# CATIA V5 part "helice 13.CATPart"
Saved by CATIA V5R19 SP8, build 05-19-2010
Part number: helice 13
Bounding box of the stored display mesh (mm): x -17.321 to 17.321, y -30 to 195, z -10 to 20
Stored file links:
  G:\EU_thinkMotion\CFAO_2010\MMS_groupe2\MMS_groupe2\A reprendre\splanchenault\Planchenault\helice 13.CATPart
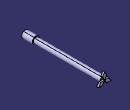
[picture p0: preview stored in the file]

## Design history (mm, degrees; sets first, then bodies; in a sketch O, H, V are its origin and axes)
Body1 (main body)
  Sketch1 on yz-plane, origin (0, 0, 0), H (0, 1, 0), V (0, 0, 1)
    line L1 (0, 0) -> (-30, 0)
    line L2 (-30, 0) -> (-30, 10)
    line L3 (-30, 10) -> (0, 10)
    line L4 (0, 10) -> (0, 7.5)
    line L5 (0, 7.5) -> (190, 7.5)
    line L6 (190, 7.5) -> (190, 0)
    line L7 (190, 0) -> (0, 0)
    length L6 = 7.5
    length L2 = 10
    horizontal: L1 H, L3 H, L5 H, L7 H
    vertical: L2 V, L4 V, L6 V
  Shaft1: profile Sketch1, axis Sketch1.L7, angle 360
  Sketch2 on face of Shaft1 from Sketch1.L6, origin (0, 190, 0), H (-1, 0, 0), V (0, 0, 1)
    construction line L1 (19.3649, -11.1803) -> (-19.3649, 11.1803)
    axis line L2 (-19.3649, -11.1803) -> (19.3649, 11.1803)
    line L3 (0, 0) -> (5.7735, 10)
    point P5 (5.7735, 10)
    line L4 (5.7735, 10) -> (0, 20)
    point P6 (0, 20)
    line L5 (0, 20) -> (-5.7735, 10)
    point P7 (-5.7735, 10)
    line L6 (-5.7735, 10) -> (0, 0)
    point P8 (-11.547, 0)
    point P9 (-17.3205, -10)
    line L7 (-17.3205, -10) -> (-11.547, 0)
    point P10 (-5.7735, -10)
    line L8 (-5.7735, -10) -> (-17.3205, -10)
    point P11 (0, 0)
    line L9 (0, 0) -> (-5.7735, -10)
    line L10 (-11.547, 0) -> (0, 0)
    point P12 (5.7735, -10)
    point P13 (17.3205, -10)
    line L11 (17.3205, -10) -> (5.7735, -10)
    point P14 (11.547, 0)
    line L12 (11.547, 0) -> (17.3205, -10)
    point P15 (0, 0)
    line L13 (0, 0) -> (11.547, 0)
    line L14 (5.7735, -10) -> (0, 0)
    angle L1 V = 60
    angle L2 V = 60
    coincidence: L2 O, O P11, O P15, P11 P15
    perpendicularity: L3 L1, L4 L2
    parallelism: L5 L3, L6 L4
    symmetry: P7 P8 L1, P6 P9 L1, L5 L7 L1, P5 P10 L1, L4 L8 L1, O P11 L1, L3 L9 L1, L6 L10 L1, P7 P12 L2, P6 P13 L2, L5 L11 L2, P5 P14 L2, L4 L12 L2, O P15 L2, L3 L13 L2, L6 L14 L2
  Pad1: profile Sketch2, direction (0, 1, 0), length 5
